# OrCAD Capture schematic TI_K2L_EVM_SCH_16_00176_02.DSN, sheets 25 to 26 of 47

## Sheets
25 PAGE42 : K2L_POWER SECTION 1: size C; title: 12v input (fused), 12v to 3p3v MP, K2L VID, 1p8 to VPP1p8 switch, 3v3Aux to 3v3, FMC1 Power (fuse),
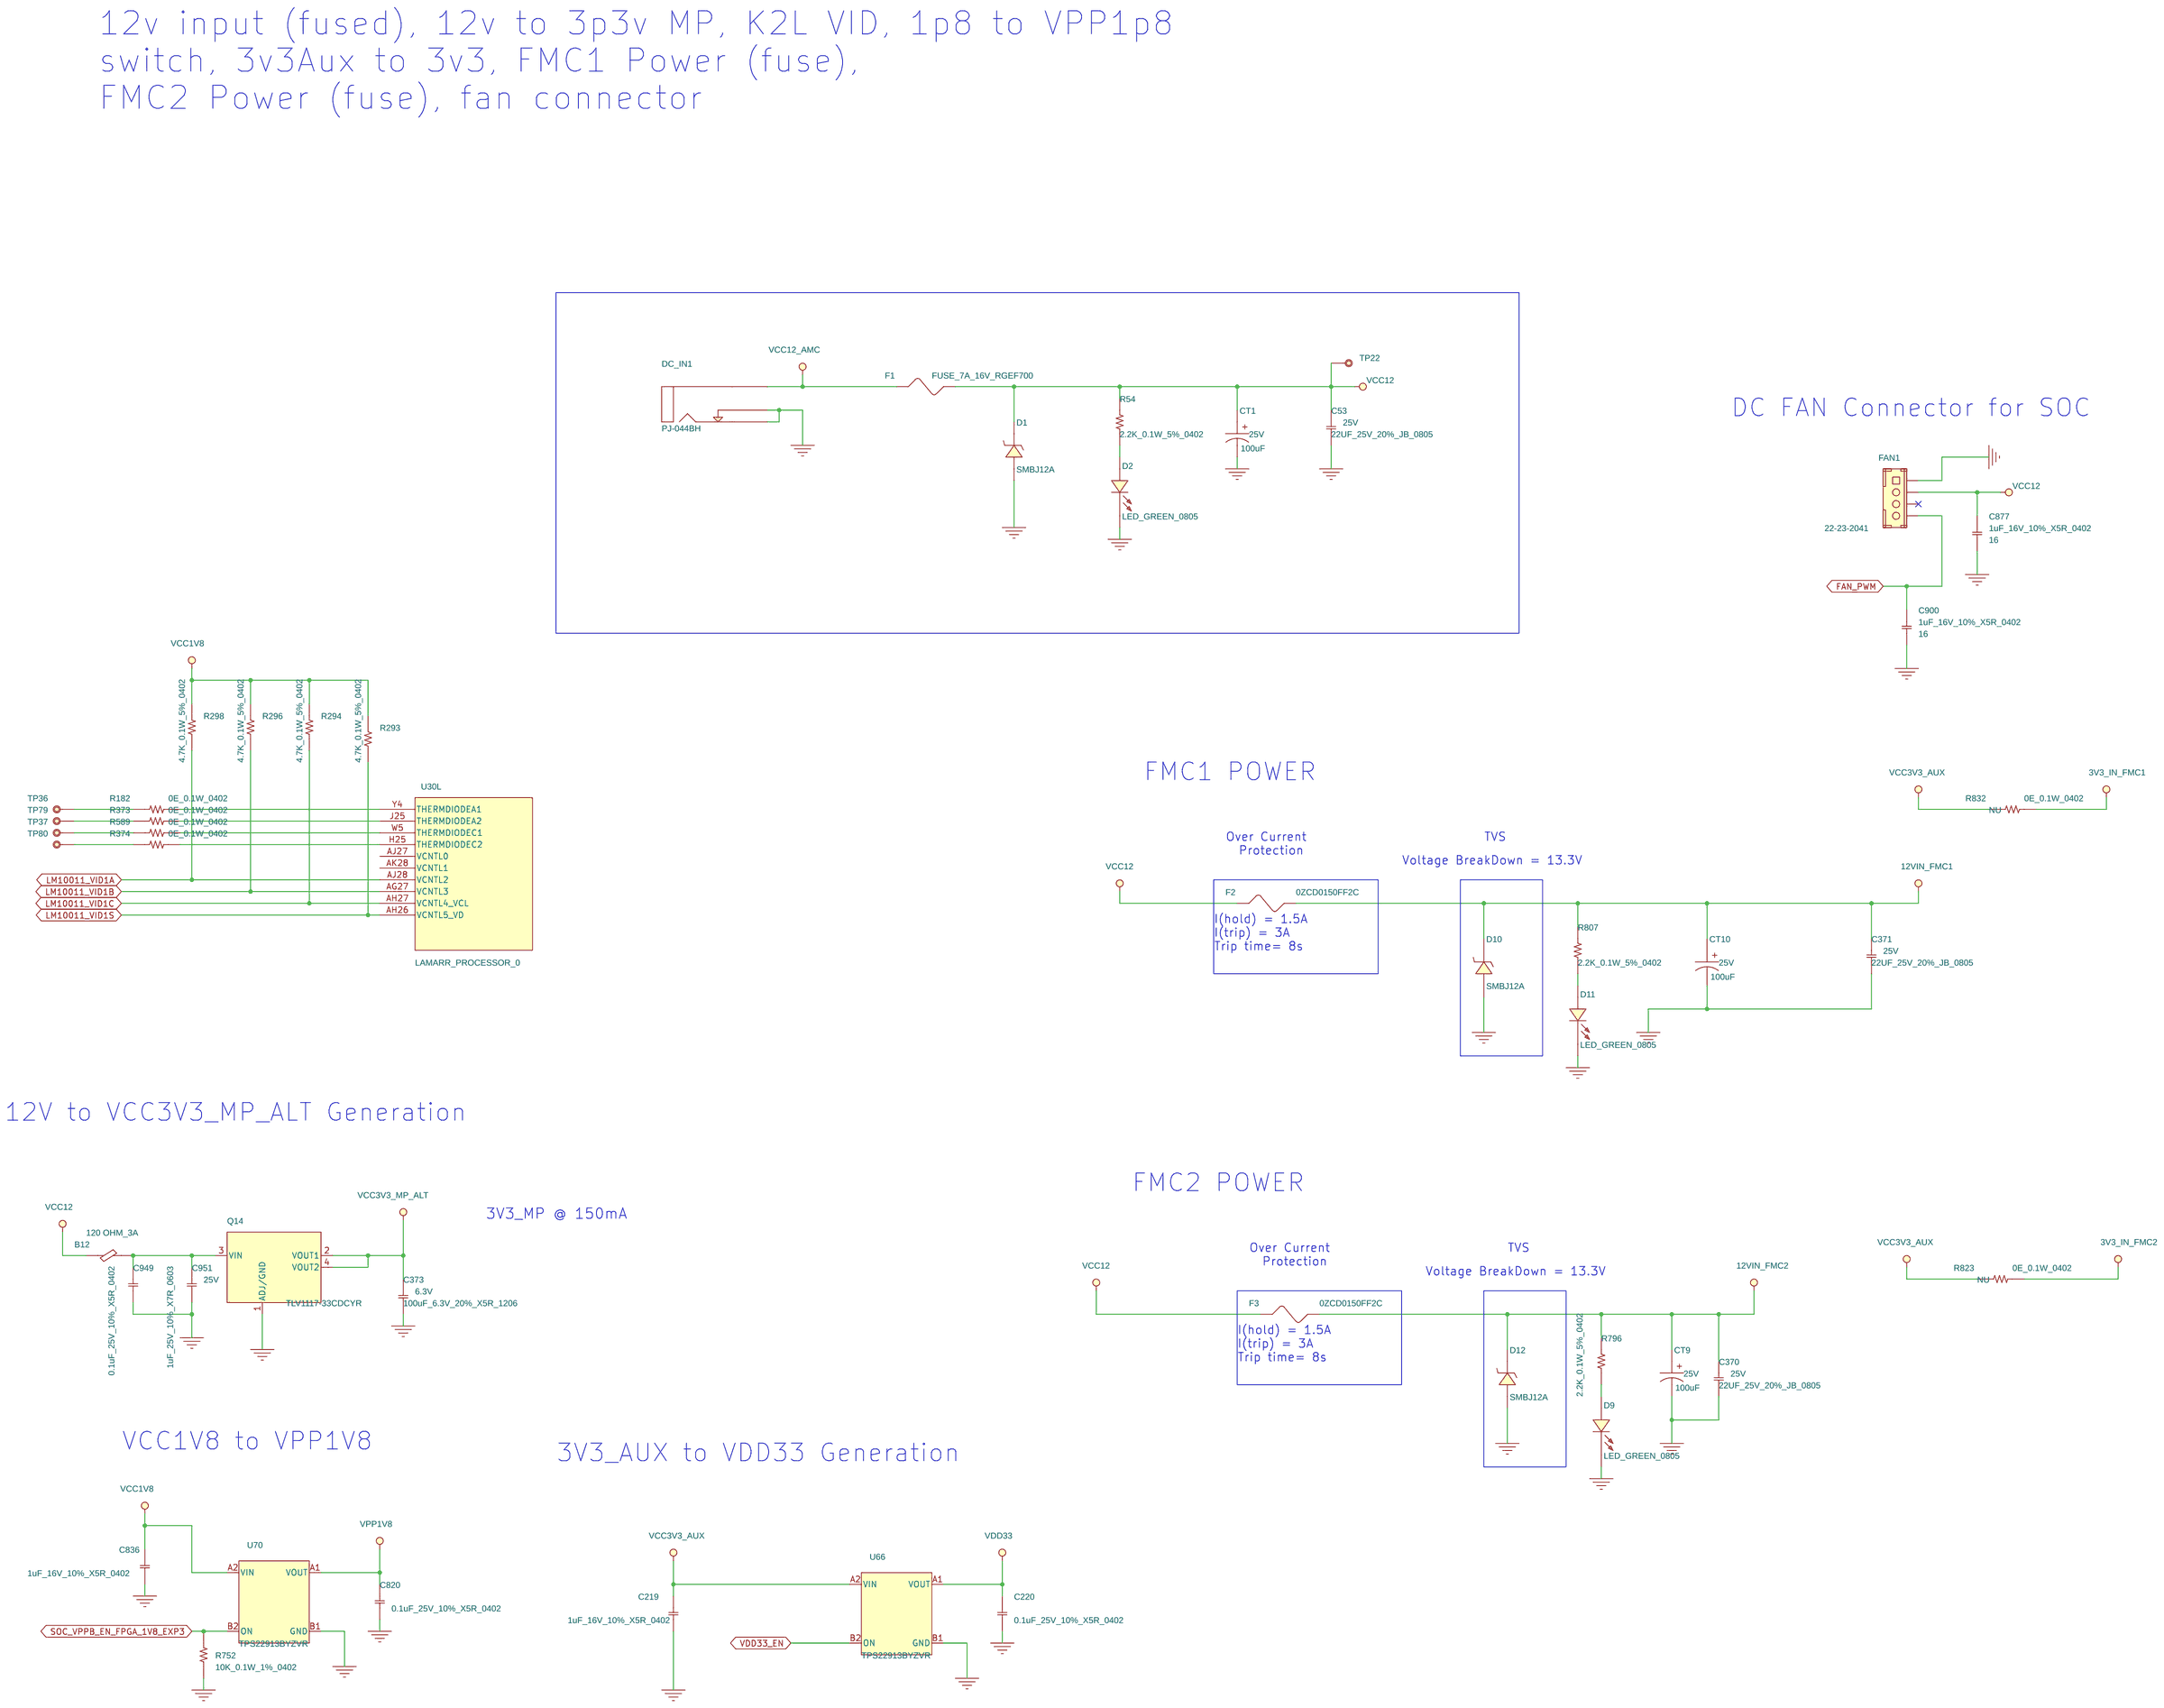
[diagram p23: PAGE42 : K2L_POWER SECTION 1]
26 PAGE26 : K2L_EXPANSION_CONN: size C; title: Expansion Connector, I2C SOC to Expander 1.8v/3.3vAux
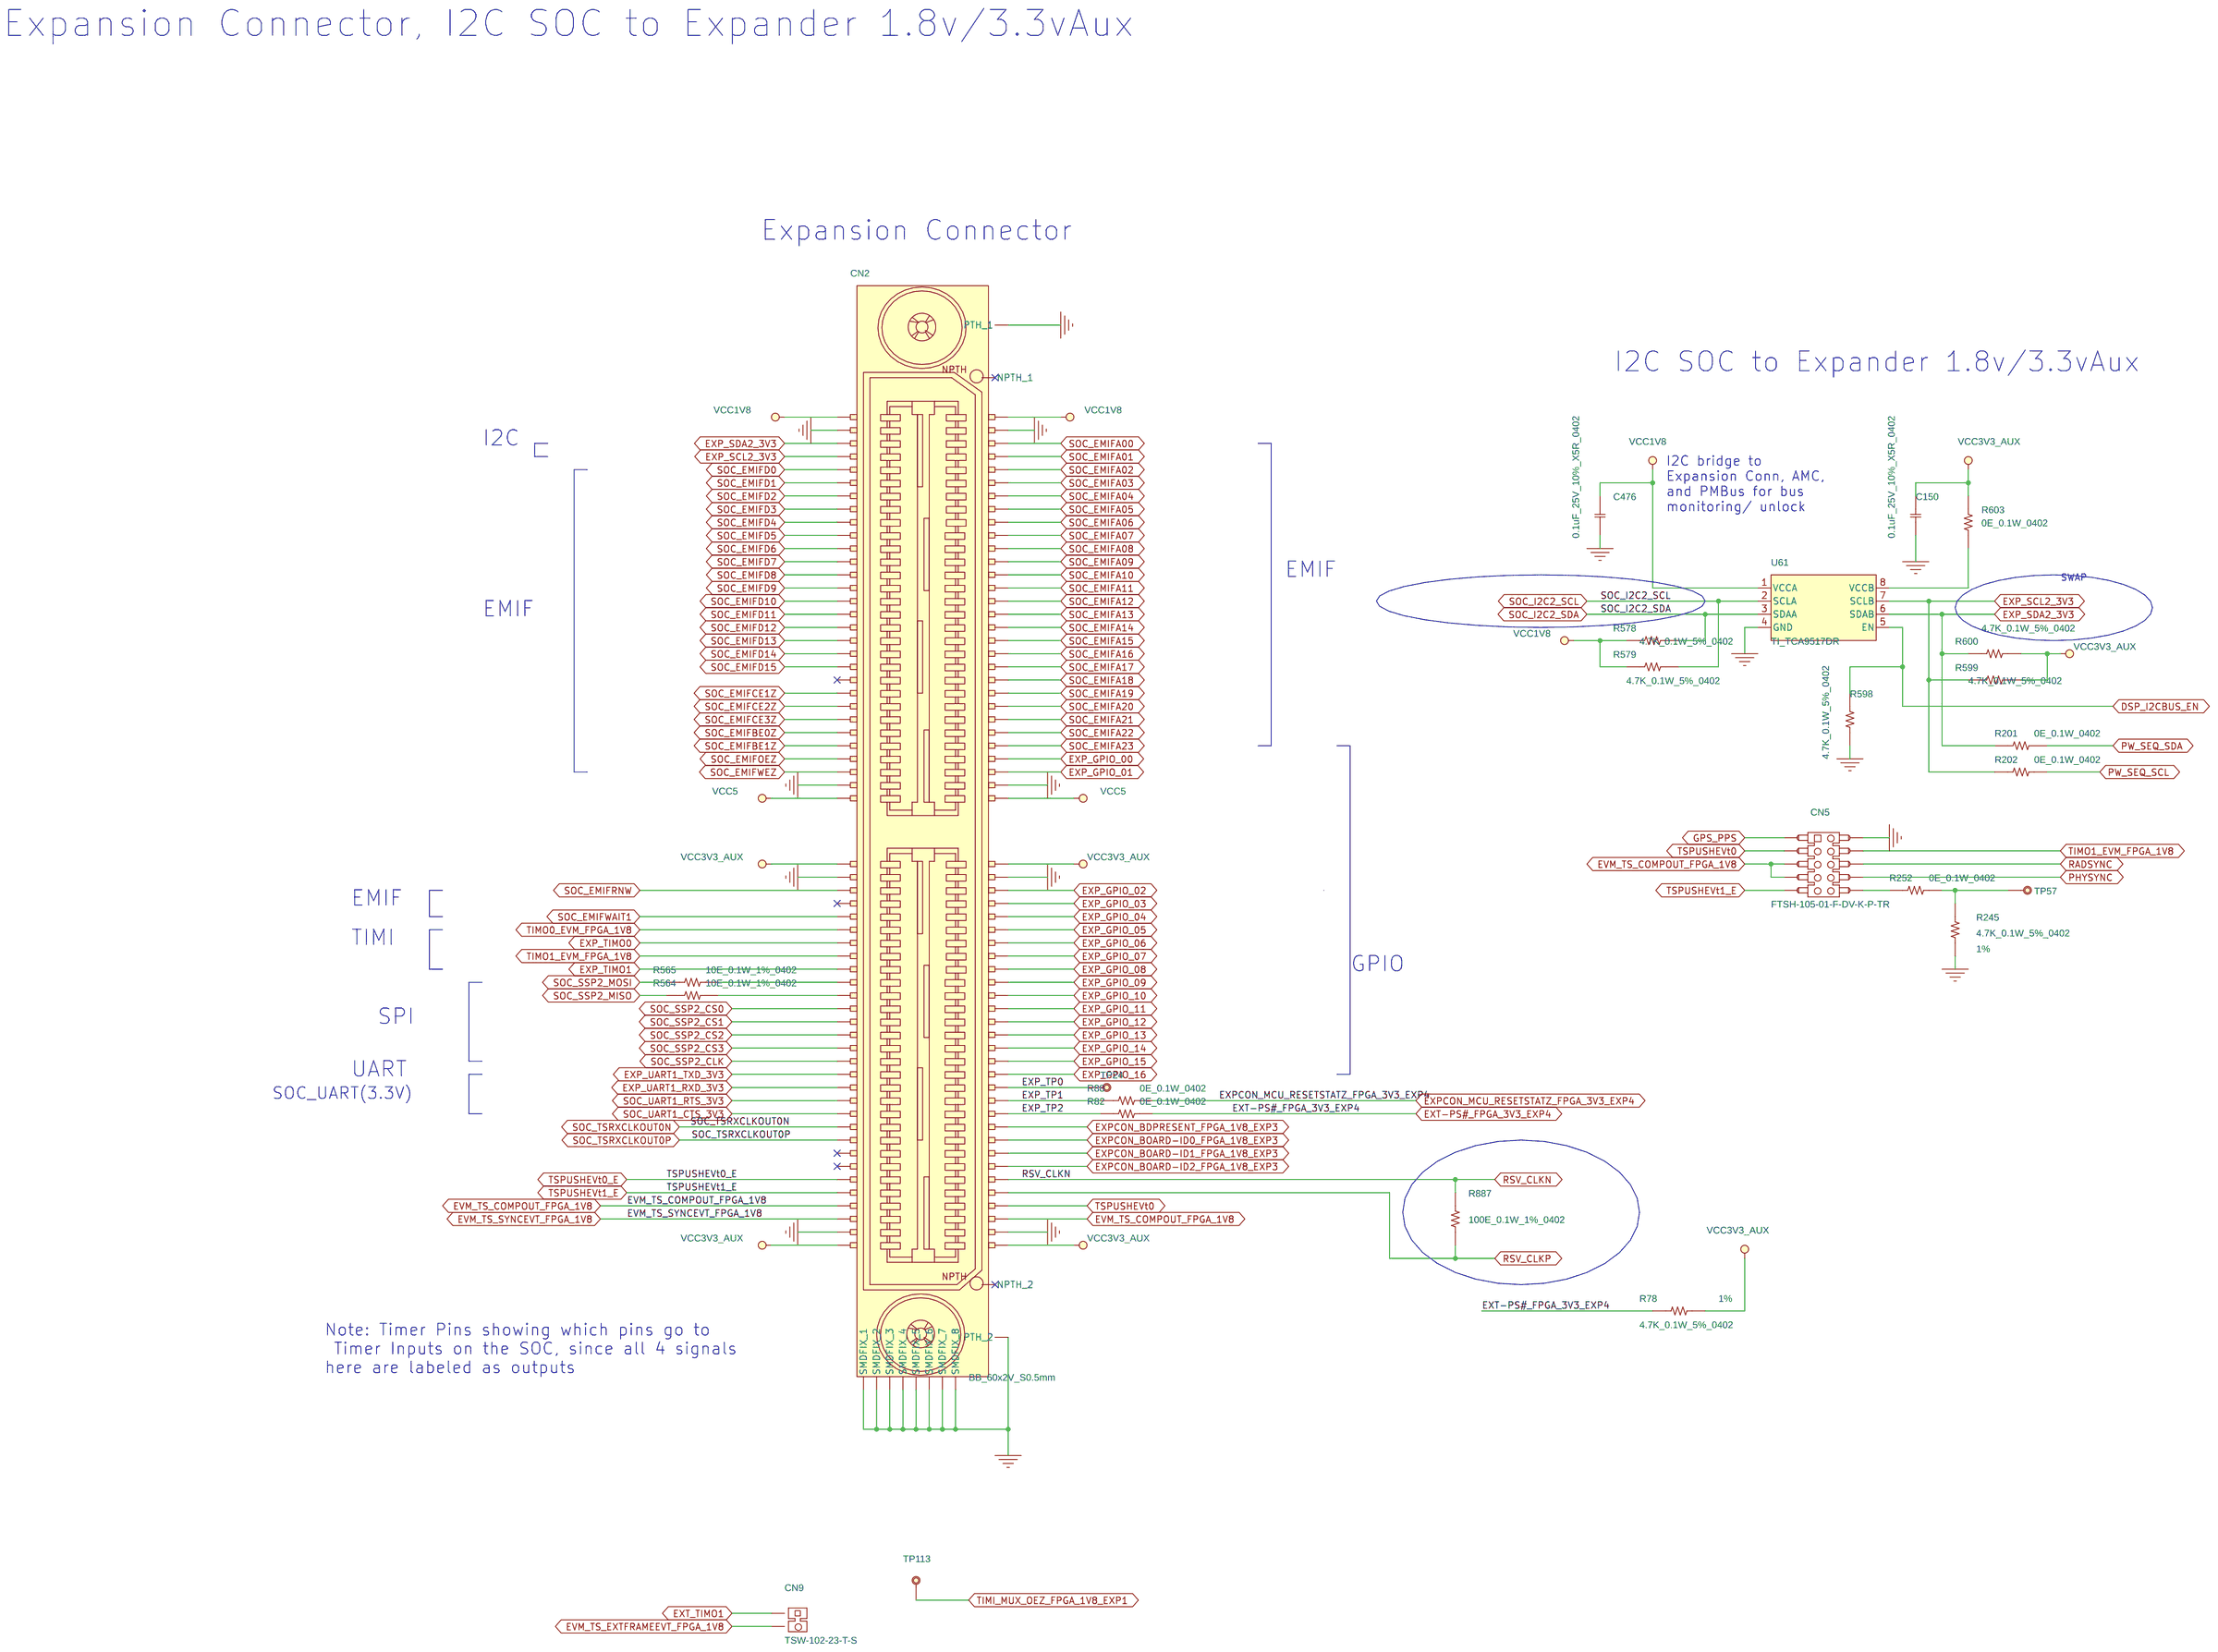
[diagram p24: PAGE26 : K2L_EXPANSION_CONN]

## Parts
sheet PAGE24 : K2L_JTAG
U30  LAMARR_PROCESSOR_0  [SKTBGA_Z3566_SS900-RHFB-BGA080]  (sections A,B,C,D,E,F,G,H,I,J,K,L,M,N,O,P,Q,R,S,T,U)
sheet PAGE26 : K2L_EXPANSION_CONN
C150  0.1uF_25V_10%_X5R_0402  [C0402]
C476  0.1uF_25V_10%_X5R_0402  [C0402]
CN2  BB_60x2V_S0.5mm  [BB_60x2P_20_2225x285_F]
CN5  FTSH-105-01-F-DV-K-P-TR  [HD_5x2P_50_H235]
CN9  TSW-102-23-T-S  [SAMTSW-102-22-T-S]
R78  4.7K_0.1W_5%_0402  [R0402]
R82  0E_0.1W_0402  [R0402]
R88  0E_0.1W_0402  [R0402]
R201  0E_0.1W_0402  [R0402]
R202  0E_0.1W_0402  [R0402]
R245  4.7K_0.1W_5%_0402  [R0402]
R252  0E_0.1W_0402  [R0402]
R564  10E_0.1W_1%_0402  [R0402]
R565  10E_0.1W_1%_0402  [R0402]
R578  4.7K_0.1W_5%_0402  [R0402]
R579  4.7K_0.1W_5%_0402  [R0402]
R598  4.7K_0.1W_5%_0402  [R0402]
R599  4.7K_0.1W_5%_0402  [R0402]
R600  4.7K_0.1W_5%_0402  [R0402]
R603  0E_0.1W_0402  [R0402]
R887  100E_0.1W_1%_0402  [R0402]
TP24  TP  [TP-S40]
TP57  TP  [TP-S40]
TP113  TP  [TP-S40]
U61  TI_TCA9517DR  [SOIC_8P_50_193X236]
sheet PAGE42 : K2L_POWER SECTION 1
B12  120 OHM_3A  [L0603]
C53  22UF_25V_20%_JB_0805  [C0805]
C219  1uF_16V_10%_X5R_0402  [C0402]
C220  0.1uF_25V_10%_X5R_0402  [C0402]
C370  22UF_25V_20%_JB_0805  [C0805]
C371  22UF_25V_20%_JB_0805  [C0805]
C373  100uF_6.3V_20%_X5R_1206  [C1206-1]
C820  0.1uF_25V_10%_X5R_0402  [C0402]
C836  1uF_16V_10%_X5R_0402  [C0402]
C877  1uF_16V_10%_X5R_0402  [C0402]
C900  1uF_16V_10%_X5R_0402  [C0402]
C949  0.1uF_25V_10%_X5R_0402  [C0402]
C951  1uF_25V_10%_X7R_0603  [C0603]
CT1  100uF  [CT7343]
CT9  100uF  [CT7343]
CT10  100uF  [CT7343]
D1  SMBJ12A  [DIO_DO214AA_SMB]
D2  LED_GREEN_0805  [LED_LTST-C171]
D9  LED_GREEN_0805  [LED_LTST-C171]
D10  SMBJ12A  [DIO_DO214AA_SMB]
D11  LED_GREEN_0805  [LED_LTST-C171]
D12  SMBJ12A  [DIO_DO214AA_SMB]
DC_IN1  PJ-044BH  [CUI_PJ-044BH]
F1  FUSE_7A_16V_RGEF700  [PTC_RGEF700]
F2  0ZCD0150FF2C  [FUSE_0ZCD0150FF2C]
F3  0ZCD0150FF2C  [FUSE_0ZCD0150FF2C]
FAN1  22-23-2041  [MOL22-23-2041]
Q14  TLV1117-33CDCYR  [SOT-223]
R54  2.2K_0.1W_5%_0402  [R0402]
R182  0E_0.1W_0402  [R0402]
R293  4.7K_0.1W_5%_0402  [R0402]
R294  4.7K_0.1W_5%_0402  [R0402]
R296  4.7K_0.1W_5%_0402  [R0402]
R298  4.7K_0.1W_5%_0402  [R0402]
R373  0E_0.1W_0402  [R0402]
R374  0E_0.1W_0402  [R0402]
R589  0E_0.1W_0402  [R0402]
R752  10K_0.1W_1%_0402  [R0402]
R796  2.2K_0.1W_5%_0402  [R0402]
R807  2.2K_0.1W_5%_0402  [R0402]
R823  0E_0.1W_0402  [R0402]
R832  0E_0.1W_0402  [R0402]
TP22  TP  [TP-S40]
TP36  TP  [TP-S40]
TP37  TP  [TP-S40]
TP79  TP  [TP-S40]
TP80  TP  [TP-S40]
U66  TPS22913BYZVR  [dsbga50p_0p9x0p9_4]
U70  TPS22913BYZVR  [dsbga50p_0p9x0p9_4]

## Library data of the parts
U30 = LAMARR_PROCESSOR_7: LAMARR-SoC 900BGA 4DSP + 2ARM; Color: Default; Distributor_name: TBD; Distributor_part_number: TBD; EIC Part#: TBD; Location X-Coordinate: 0; Location Y-Coordinate: 0; Manufacture: TI; Manufacture Part Number: TCI6630K2L; Manufacture(English): TI; Manufacture_Part_Number: TCI6630K2L; Manufacturer: TI; Manufacturer_Part_No: TCI6630K2L; Mfg: TI; Mfg Part#: TBD; Mfr_name: TI; Mfr_part_number: LAMARR-SoC; Price @ 1: TBD; Price @ 10K: TBD; Price @ 1K: TBD; Primitive: DEFAULT; SPLIT_INST: TRUE; SWAP_INFO: (S1+S2+S3+S4+S5+S6+S7+S8+S9+S10+S11+S12+S13+S14+S15+S16+S17+S18+S19+S20+S21); Vendor: TBD; Vendor_Part_No: TBD; eI Part#: TBD
C150 C476 = 11_C_0: CAP CER 0.1UF 25V 10% X5R 0402; Avalue_Part_Number: E1123510400H; Distributor_name: DIGIKEY; Distributor_part_number: 445-4964-1-ND; EIC Part#: 03_00470_02; MOUNTED: <MOUNTED>; Manufacture: TDK Corporation; Manufacture Part Number: C1005X5R1E104K050BC; Manufacture(English): TDK Corporation; Manufacture_Part_Number: GRM155R71C104KA88D; Manufacturer: TDK Corporation; Manufacturer_Part_No: C1005X5R1E104K050BC; Mfg: Murata Electronics North America; Mfg Part#: 03_00470_02; Mfr_name: TDK Corporation; Mfr_part_number: C1005X5R1E104K050BC; Package: 0402; Price @ 1: 0.10000; Price @ 1K: 0.00420; ProcessType: SMT; Tolerance: 10%; Vendor: DIGIKEY; Vendor Part#: 445-4964-1-ND; Vendor_Part_No: 445-4964-1-ND; eI Part#: 03_00470_02
CN2 = 1654_BB_60X2P_4HOLD_QSH_0: CONN RECPT 120POS 0.5MM SMT; Distributor_name: DIGIKEY; Distributor_part_number: QSH-060-01-L-D-A-RT1-ND; EIC Part#: TBD; Manufacture: Samtec Inc; Manufacture Part Number: QSH-060-01-L-D-A-RT1; Manufacture(English): Samtec Inc; Manufacture_Part_Number: QSH-060-01-L-D-A-RT1; Manufacturer: Samtec Inc; Manufacturer_Part_No: QSH-060-01-L-D-A-RT1; Mfg: Samtec Inc; Mfg Part#: TBD; Mfr_name: Samtec Inc; Mfr_part_number: QSH-060-01-L-D-A-RT1; Package: BB60x2P-S0.5; Part_Number: 1654010650-01; Price @ 1K: 12.95750; ProcessType: SMT; Vendor: DIGIKEY; Vendor_Part_No: QSH-060-01-L-D-A-RT1-ND; eI Part#: TBD
CN5 = 1653_HD_5X2P_0: CONN HEADER 10POS DUAL .05 SMD; AVL_Part: AVL; Distributor_name: DIGIKEY; Distributor_part_number: FTSH-105-01-F-DV-K-P-TR-ND; EIC Part#: TBD; Manufacture: Samtec Inc; Manufacture(English): Samtec Inc; Manufacturer: Samtec Inc; Mfg: Samtec Inc; Mfg Part#: TBD; Mfr_name: Samtec Inc; Package: PH5x2P-S1.27; Part_Number: 1653004493; Price @ 1: 2.19000; Price @ 10K: 1.88000; Price @ 1K: 2.00000; ProcessType: SMT; Vendor: DIGIKEY; Vendor_Part_No: FTSH-105-01-F-DV-K-P-TR-ND; eI Part#: TBD
CN9 = 1653_HD_2P_D_0: CONN HEADER 2POS .100 SNGL TIN; AVL_Part: AVL; Advansus_Part_Number: 12G06010002DAD; Avalue_Part_Number: E1653002101R; Distributor_name: DIGIKEY; Distributor_part_number: SAM1075-02-ND; EIC Part#: 09_00957_01; Manufacture: Samtec Inc; Manufacture(English): Samtec Inc; Manufacturer: Samtec Inc; Mfg: Samtec Inc; Mfg Part#: 09_00957_01; Mfr_name: Samtec Inc; Package: PH2x1P-2.00; Part_Number: 1653002101-03; Price @ 1: 0.49000; Price @ 10K: 0.21284; Price @ 1K: 0.24263; ProcessType: DIP; Vendor: DIGIKEY; Vendor_Part_No: SAM1075-02-ND; eI Part#: TBD
R78 R245 R578 R579 R599 R600 = 10_R_0: RES 4.7K OHM 1/10W 5% 0402 SMD; AVL_Part: AVL; Advansus_Part_Number: 10G212470114030; Characteristic: 1%; Distributor_name: DIGIKEY; Distributor_part_number: P4.7KJCT-ND; EIC Part#: 02_00023_01; MOUNTED: <MOUNTED>; Manufacture: Panasonic - ECG; Manufacture Part Number: ERJ-2GEJ472X; Manufacture(English): Panasonic - ECG; Manufacture_Part_Number: ERJ-2GEJ472X; Manufacturer: Panasonic - ECG; Manufacturer_Part_No: ERJ-2GEJ472X; Mfg: Panasonic Electronic Components; Mfg Part#: 02_00266_01; Mfr_name: Panasonic - ECG; Mfr_part_number: ERJ-2GEJ472X; Package: 0402; Part_Number: 1000000558-04; Price @ 1: 0.10000; Price @ 10K: 0.00347; Price @ 1K: 0.00672; ProcessType: SMT; Tolerance: 1%; Vendor: DIGIKEY; Vendor_Part_No: P4.7KJCT-ND; eI Part#: 02_00023_01
R82 R88 = 10_R_0: RES 0.0 OHM 1/10W JUMP 0402 SMD; Characteristic: 5%; Distributor_name: DIGIKEY; Distributor_part_number: P0.0JCT-ND; EIC Part#: 02_00019_01; Manufacture: Panasonic - ECG; Manufacture Part Number: ERJ-2GE0R00X; Manufacture(English): Panasonic - ECG; Manufacture_Part_Number: ERJ-2GE0R00X; Manufacturer: Panasonic - ECG; Manufacturer_Part_No: ERJ-2GE0R00X; Mfg: Panasonic Electronic Components; Mfg Part#: 02_00019_01; Mfr_name: Panasonic - ECG; Mfr_part_number: ERJ-2GE0R00X; Package: 0402; Part_Number: 105A700004; Price @ 1: 0.05000; Price @ 10K: 0.00248; Price @ 1K: 0.00480; ProcessType: SMT; Tolerance: 5%; Vendor: DIGIKEY; Vendor_Part_No: P0.0JCT-ND; eI Part#: 02_00019_01
R182 R201 R202 R252 R373 R374 R589 = 10_R_0: RES 0.0 OHM 1/10W JUMP 0402 SMD; Alt Mfg: Yageo; Distributor_name: DIGIKEY; Distributor_part_number: P0.0JCT-ND; EIC Part#: 02_00019_01; Manufacture: Panasonic - ECG; Manufacture Part Number: ERJ-2GE0R00X; Manufacture(English): Panasonic - ECG; Manufacture_Part_Number: ERJ-2GE0R00X; Manufacturer: Panasonic - ECG; Manufacturer_Part_No: ERJ-2GE0R00X; Mfg Part#: 02_00019_01; Mfr_name: Panasonic - ECG; Mfr_part_number: ERJ-2GE0R00X; Oper. Temp. Range: -55C to 125C; Package: 0402; ProcessType: SMT; Remark: Alt part is 1/16W; RoHS: Yes; Tolerance: 5%; Vendor: DIGIKEY; Vendor Part#: P0.0JCT-ND; Vendor_Part_No: P0.0JCT-ND; eI Part#: 02_00019_01
R564 R565 = 10_R_0: RES 10.0 OHM 1/10W 1% 0402 SMD; Characteristic: 5%; Distributor_name: DIGIKEY; Distributor_part_number: P10.0LCT-ND; EIC Part#: 02_00348_01; Manufacture: Panasonic - ECG; Manufacture Part Number: ERJ-2RKF10R0X; Manufacture(English): Panasonic - ECG; Manufacture_Part_Number: ERJ-2RKF10R0X; Manufacturer: Panasonic - ECG; Manufacturer_Part_No: ERJ-2RKF10R0X; Mfg: Panasonic Electronic Components; Mfg Part#: ERJ-2RKF10R0X; Mfr_name: Panasonic - ECG; Mfr_part_number: ERJ-2RKF10R0X; Package: 0402; Part_Number: 105A701004; Price @ 1: 0.10000; Price @ 10K: 0.00248; Price @ 1K: 0.00480; ProcessType: SMT; Tolerance: 5%; Vendor: DIGIKEY; Vendor_Part_No: P10.0LCT-ND; eI Part#: 02_00348_01
R598 = 10_R_0: RES 4.7K OHM 1/10W 5% 0402 SMD; Alt Mfg: Yageo; Alt Mfg Part#: RC0402JR-074K7L; Distributor_name: DIGIKEY; Distributor_part_number: P4.7KJCT-ND; EIC Part#: 02_00023_01; Manufacture: Panasonic - ECG; Manufacture Part Number: ERJ-2GEJ472X; Manufacture(English): Panasonic - ECG; Manufacture_Part_Number: ERJ-2GEJ472X; Manufacturer: Panasonic - ECG; Manufacturer_Part_No: ERJ-2GEJ472X; Mfg Part#: 02_00023_01; Mfr_name: Panasonic - ECG; Mfr_part_number: ERJ-2GEJ472X; Oper. Temp. Range: -55C to 125C; Package: 0402; ProcessType: SMT; Remark: Alt part is 1/16W; RoHS: Yes; Tolerance: 1%; Vendor: DIGIKEY; Vendor Part#: P4.7KJCT-ND; Vendor_Part_No: P4.7KJCT-ND; eI Part#: 02_00023_01
R603 = 10_R_0: RES 0.0 OHM 1/10W JUMP 0402 SMD; Characteristic: 5%; Distributor_name: DIGIKEY; Distributor_part_number: P0.0JCT-ND; EIC Part#: 02_00019_01; MOUNTED: <MOUNTED>; Manufacture: Panasonic - ECG; Manufacture Part Number: ERJ-2GE0R00X; Manufacture(English): Panasonic - ECG; Manufacture_Part_Number: ERJ-2GE0R00X; Manufacturer: Panasonic - ECG; Manufacturer_Part_No: ERJ-2GE0R00X; Mfg: Panasonic Electronic Components; Mfg Part#: 02_00019_01; Mfr_name: Panasonic - ECG; Mfr_part_number: ERJ-2GE0R00X; Package: 0402; Part_Number: 105A700004; Price @ 1: 0.05000; Price @ 10K: 0.00248; Price @ 1K: 0.00480; ProcessType: SMT; Tolerance: 5%; Vendor: DIGIKEY; Vendor_Part_No: P0.0JCT-ND; eI Part#: 02_00019_01
R887 = 10_R_0: RES 100 OHM 1/10W 1% 0402 SMD; Characteristic: 1%; Distributor_name: DIGIKEY; Distributor_part_number: P100LCT-ND; EIC Part#: 02_00043_02; Manufacture: Panasonic - ECG; Manufacture Part Number: ERJ-2RKF1000X; Manufacture(English): Panasonic - ECG; Manufacture_Part_Number: ERJ-2RKF1000X; Manufacturer: Panasonic - ECG; Manufacturer_Part_No: ERJ-2RKF1000X; Mfg: Panasonic Electronic Components; Mfg Part#: 02_00043_02; Mfr_name: Panasonic - ECG; Mfr_part_number: ERJ-2RKF1000X; Package: 0402; Part_Number: 105A510004; Price @ 1: 0.10000; Price @ 10K: 0.00347; Price @ 1K: 0.00672; ProcessType: SMT; Tolerance: 1%; Vendor: DIGIKEY; Vendor_Part_No: P100LCT-ND; eI Part#: 02_00019_01
TP22 TP24 TP36 TP37 TP57 TP79 TP80 = 00_TP28_0: TEST PAD TP; Advansus_Part_Number: 0030000003; Avalue_Part_Number: 0030000003; Distributor_name: NA; Distributor_part_number: NA; EIC Part#: NA; Manufacture: NA; Manufacture Part Number: NA; Manufacture(English): NA; Manufacture_Part_Number: NA; Manufacturer: NA; Manufacturer_Part_No: NA; Mfg: NA; Mfg Part#: NA; Mfr_name: NA; Mfr_part_number: NA; Part_Number: 0030000003; Price @ 1: NA; Price @ 10K: NA; Price @ 1K: NA; ProcessType: SMT; Vendor: NA; Vendor_Part_No: NA; eI Part#: NA
TP113 = 00_TP28_0: TEST PAD TP; Advansus_Part_Number: 0030000003; Avalue_Part_Number: 0030000003; Distributor_name: NA; Distributor_part_number: NA; EIC Part#: NA; Manufacture: NA; Manufacture Part Number: NA; Manufacture(English): NA; Manufacture_Part_Number: NA; Manufacturer: NA; Manufacturer_Part_No: NA; Mfg: NA; Mfg Part#: NA; Mfr_name: NA; Mfr_part_number: NA; Part_Number: 0030000003; Price @ 1: NA; Price @ 10K: NA; Price @ 1K: NA; ProcessType: SMT; Vendor: NA; Vendor_Part_No: NA; eI Part#: TBD
U61 = 141_TI_PCA9517DR_0: IC LVL-TRANSL I2C BUS REP 8-SOIC; AVL_Part: AVL; Alternate_Mfr: TI; Alternate_Partno: TCA9517DR; Distributor_name: DIGIKEY; Distributor_part_number: 296-23734-1-ND; EIC Part#: TBD; Manufacture: TI; Manufacture Part Number: PCA9517DR; Manufacture(English): TI; Manufacture_Part_Number: PCA9517DR; Manufacturer: TI; Manufacturer_Part_No: PCA9517DR; Mfg: TI; Mfg Part#: TBD; Mfr_name: TI; Mfr_part_number: PCA9517DR; Package: SOIC8; Part_Number: 1410015122; Price @ 1: 2.94000; Price @ 10K: 1.35660; Price @ 1K: 1.46880; ProcessType: SMT; Vendor: DIGIKEY; Vendor_Part_No: 296-23734-1-ND; eI Part#: 01_00923_01
B12 = 1212_BEAD_0: FILTER CHIP 120 OHM 3A 0603; Distributor_name: DIGIKEY; Distributor_part_number: 490-3996-1-ND; EIC Part#: 04_00405_01; Manufacture: Murata; Manufacture Part Number: BLM18SG121TN1D; Manufacture(English): Murata; Manufacture_Part_Number: BLM18SG121TN1D; Manufacturer: Murata; Manufacturer_Part_No: BLM18SG121TN1D; Mfg: Murata Electronics North America; Mfg Part#: 04_00405_01; Mfr_name: Murata; Mfr_part_number: BLM18SG121TN1D; Part_Number: 1212002506; Price @ 1: 0.14000; Price @ 10K: 0.03173; Price @ 1K: 0.03878; RoHS: Yes; Vendor: DIGIKEY; Vendor Part#: 490-3996-1-ND; Vendor_Part_No: 490-3996-1-ND; eI Part#: 04_00405_01
C53 C370 C371 = 11_C_0: CAP CER 22UF 25V 20% JB 0805; Alternate_Mfr: Samsung; Alternate_Partno: CL21A226MAQNNNE; Distributor_name: DIGIKEY; Distributor_part_number: 445-11475-2-ND; EIC Part#: 03_00586_01; Manufacture: TDK Corporation; Manufacture Part Number: C2012JB1E226M125AC; Manufacture(English): TDK Corporation; Manufacture_Part_Number: C2012JB1E226M125AC; Manufacturer: TDK Corporation; Manufacturer_Part_No: C2012JB1E226M125AC; Mfg: TDK Corporation; Mfg Part#: C2012JB1E226M125AC; Mfr_name: TDK Corporation; Mfr_part_number: C2012JB1E226M125AC; Oper. Temp. Range: -55C to 85C; Package: 0805; Price @ 1: 1.09000; Price @ 10K: 0.26265; Price @ 1K: 0.37647; ProcessType: SMT; RoHS: Yes; Tolerance: 10%; Vendor: DIGIKEY; Vendor Part#: 490-5527-1-ND; Vendor_Part_No: 03_00586_01; Voltage: 25V; eI Part#: 03_00586_01
C219 C836 = 11_C_12: CAP CER 1UF 16V 10% X5R 0402; Characteristic: <Characteristic>; Distributor_name: DIGIKEY; Distributor_part_number: 445-4978-1-ND; EIC Part#: 03_00355_04; Manufacture: TDK Corporation; Manufacture Part Number: C1005X5R1C105K050BC; Manufacture(English): TDK Corporation; Manufacture_Part_Number: C1005X5R1C105K050BC; Manufacturer: TDK Corporation; Manufacturer_Part_No: C1005X5R1C105K050BC; Mfg: TDK Corporation; Mfg Part#: C1005X5R1C105K050BC; Mfr_name: TDK Corporation; Mfr_part_number: C1005X5R1C105K050BC; Oper. Temp. Range: -55C to 85C; Package: 0402; Price @ 1: 0.12000; Price @ 10K: 0.01600; Price @ 1K: 0.02200; ProcessType: SMT; RoHS: Yes; Tolerance: 10%; Vendor: DIGIKEY; Vendor Part#: 445-4978-1-ND; Vendor_Part_No: 445-4978-1-ND; Voltage: 6.3V; eI Part#: 03_00355_04
C220 C820 = 11_C_12: CAP CER 0.1UF 25V 10% X5R 0402; Alt Mfg: Taiyo Yuden; Distributor_name: DIGIKEY; Distributor_part_number: 445-4964-1-ND; EIC Part#: 03_00470_02; Manufacture: TDK Corporation; Manufacture Part Number: C1005X5R1E104K050BC; Manufacture(English): TDK Corporation; Manufacture_Part_Number: GRM155R61E104KA87D; Manufacturer: TDK Corporation; Manufacturer_Part_No: C1005X5R1E104K050BC; Mfg: Murata Electronics North America; Mfg Part#: 03_00470_02; Mfr_name: TDK Corporation; Mfr_part_number: C1005X5R1E104K050BC; Oper. Temp. Range: -55°C ~ 85°C; Package: 0402; Price @ 1: 0.10000; Price @ 1K: 0.00960; ProcessType: SMT; RoHS: Yes; Tolerance: 10%; Vendor: DIGIKEY; Vendor Part#: 445-4964-1-ND; Vendor_Part_No: 445-4964-1-ND; eI Part#: 03_00470_02
C373 = 11_C_0: CAP CER 100UF 6.3V 20% X5R 1206; Distributor_name: DIGIKEY; Distributor_part_number: 587-1453-1-ND; EIC Part#: 03_00380_04; Manufacture: Taiyo Yuden; Manufacture Part Number: JMK316BJ107ML-T; Manufacture(English): Taiyo Yuden; Manufacture_Part_Number: JMK316BJ107ML-T; Manufacturer: Taiyo Yuden; Manufacturer_Part_No: JMK316BJ107ML-T; Mfg: Taiyo Yuden; Mfg Part#: 03_00380_04; Mfr_name: Taiyo Yuden; Mfr_part_number: JMK316BJ107ML-T; Oper. Temp. Range: -55C to 85C; Package: 1206; Price @ 1: 1.80000; Price @ 10K: 0.30450; Price @ 1K: 0.43050; ProcessType: SMT; RoHS: Yes; Tolerance: 20%; Vendor: DIGIKEY; Vendor Part#: 587-1963-1-ND; Vendor_Part_No: 587-1453-1-ND; Voltage: 6.3V; eI Part#: 03_00380_04
C877 C900 = 11_C_12: CAP CER 1UF 16V 10% X5R 0402; Characteristic: <Characteristic>; Distributor_name: DIGIKEY; Distributor_part_number: 445-4978-1-ND; EIC Part#: 03_00355_04; Manufacture: TDK Corporation; Manufacture Part Number: C1005X5R1C105K050BC; Manufacture(English): TDK Corporation; Manufacture_Part_Number: C1005X5R1C105K050BC; Manufacturer: TDK Corporation; Manufacturer_Part_No: C1005X5R1C105K050BC; Mfg: TDK Corporation; Mfg Part#: C1005X5R1C105K050BC; Mfr_name: TDK Corporation; Mfr_part_number: C1005X5R1C105K050BC; Oper. Temp. Range: -55C to 85C; Package: 0402; Price @ 1: 0.12000; Price @ 10K: 0.01600; Price @ 1K: 0.02200; ProcessType: SMT; RoHS: Yes; Tolerance: 10%; Vendor: DIGIKEY; Vendor Part#: 445-4978-1-ND; Vendor_Part_No: 445-4978-1-ND; Voltage: 16; eI Part#: 03_00355_04
C949 = 11_C_0: CAP CER 0.1UF 25V 10% X5R 0402; Alt Mfg: Taiyo Yuden; Distributor_name: DIGIKEY; Distributor_part_number: 445-4964-1-ND; EIC Part#: 03_00470_02; Manufacture: TDK Corporation; Manufacture Part Number: C1005X5R1E104K050BC; Manufacture(English): TDK Corporation; Manufacture_Part_Number: GRM155R61E104KA87D; Manufacturer: TDK Corporation; Manufacturer_Part_No: C1005X5R1E104K050BC; Mfg: Murata Electronics North America; Mfg Part#: 03_00470_02; Mfr_name: TDK Corporation; Mfr_part_number: C1005X5R1E104K050BC; Oper. Temp. Range: -55°C ~ 85°C; Package: 0402; Price @ 1: 0.10000; Price @ 1K: 0.00960; ProcessType: SMT; RoHS: Yes; Tolerance: 10%; Vendor: DIGIKEY; Vendor Part#: 445-4964-1-ND; Vendor_Part_No: 445-4964-1-ND; eI Part#: 03_00470_02
C951 = 11_C_0: CAP CER 1UF 25V 10% X5R 0603; Distributor_name: DIGIKEY; Distributor_part_number: 490-3897-1-ND; EIC Part#: 03_00161_02; Manufacture: Murata; Manufacture Part Number: GRM188R61E105KA12D; Manufacture(English): Murata; Manufacture_Part_Number: GRM188R71E105KA12D; Manufacturer: Murata; Manufacturer_Part_No: GRM188R61E105KA12D; Mfg: Murata; Mfg Part#: 03_00161_02; Mfr_name: Murata; Mfr_part_number: GRM188R61E105KA12D; Oper. Temp. Range: -55C to 85C; Package: 0603; Price @ 1: 0.38000; Price @ 10K: 0.07363; Price @ 1K: 0.09353; ProcessType: SMT; RoHS: Yes; Tolerance: 10%; Vendor: DIGIKEY; Vendor Part#: 490-3897-1-ND; Vendor_Part_No: 490-3897-1-ND; Voltage: 25V; eI Part#: 03_00161_02
CT1 CT9 CT10 = CAP_POL: CAP TANT 100UF 20V 10% 2917; Distributor_name: DIGIKEY; Distributor_part_number: 718-1774-1-ND; EIC Part#: 03_00602_01; Manufacture: Vishay; Manufacture Part Number: TR3D107K020C0080; Manufacture(English): Vishay Dale; Manufacture_Part_Number: TR3D107K020C0080; Manufacturer: Vishay Dale; Manufacturer_Part_No: TR3D107K020C0080; Mfg: Vishay Dale; Mfg Part#: TR3D107K020C0080; Mfr_name: Vishay Dale; Mfr_part_number: TR3D107K020C0080; Oper. Temp. Range: -55C to 125C; Package: 7343; RoHS: Yes; Specifications: CAP TANT 100UF 25V 10% SMD; Vendor: DIGIKEY; Vendor Part#: 718-1774-1-ND; Vendor_Part_No: 718-1774-1-ND; Voltage: 25V; eI Part#: 03_00602_01
D1 D10 D12 = Zener_Diode: TVS 600W 12V UNIDIRECT SMB; Alt Mfg: Diodes Inc; Alt Mfg Part#: SMBJ12A-13-F; Distributor_name: DIGIKEY; Distributor_part_number: SMBJ12A-TPMSCT-ND; EIC Part#: 06_00088_01; Manufacture: Micro Commercial Co; Manufacture Part Number: SMBJ12A-TP; Manufacture(English): Micro Commercial Co; Manufacture_Part_Number: SMBJ12A-TP; Manufacturer: Micro Commercial Co; Manufacturer_Part_No: SMBJ12A-TP; Mfg Part#: 06_00088_01; Mfr_name: Micro Commercial Co; Mfr_part_number: SMBJ12A-TP; Package: DO-214AA, SMB; RoHS: Yes; Specifications: TVS 600W 12V UNIDIRECT SMB; Vendor: DIGIKEY; Vendor Part#: SMBJ12A-TPMSCT-ND; Vendor_Part_No: SMBJ12A-TPMSCT-ND; eI Part#: 06_00088_01
D2 D9 D11 = LED: LED GREEN CLEAR THIN 0805 SMD; Distributor_name: DIGIKEY; Distributor_part_number: 160-1426-1-ND; EIC Part#: 06_00086_01; Manufacture: Lite-On Inc; Manufacture Part Number: LTST-C171KGKT; Manufacture(English): Lite-On Inc; Manufacture_Part_Number: LTST-C171KGKT; Manufacturer: Lite-On Inc; Manufacturer_Part_No: LTST-C171KGKT; Mfg Part#: 06_00086_01; Mfr_name: Lite-On Inc; Mfr_part_number: LTST-C171KGKT; Oper. Temp. Range: -25 to +85C; Package: 0805; RoHS: Yes; Specifications: LED GREEN CLEAR THIN 0805 SMD; Vendor: DIGIKEY; Vendor Part#: 160-1426-1-ND; Vendor_Part_No: 160-1426-1-ND; eI Part#: 06_00086_01
DC_IN1 = Power_Jack: CON PWR JCK 2.5 X 6.5MM VERT; Distributor_name: DIGIKEY; Distributor_part_number: CP-044BH-ND; EIC Part#: TBD; Manufacture: CUI Inc; Manufacture(English): CUI Inc; Manufacturer: CUI Inc; Mfg Part#: TBD; Mfr_name: CUI Inc; Vendor: DIGIKEY; Vendor Part#: CP-044BH-ND; Vendor_Part_No: CP-044BH-ND; eI Part#: TBD
F1 = Fuse: POLYSWITCH RGE SERIES 7.0A HOLD; Distributor_name: DIGIKEY; Distributor_part_number: RGEF700-ND; EIC Part#: TBD; Manufacture: TE Connectivity; Manufacture Part Number: RGEF700; Manufacture(English): TE Connectivity; Manufacture_Part_Number: RGEF700; Manufacturer: TE Connectivity; Manufacturer_Part_No: RGEF700; Mfg: TE Connectivity; Mfg Part#: RGEF700; Mfr_name: TE Connectivity; Mfr_part_number: RGEF700; Package: Radial; Vendor: DIGIKEY; Vendor Part#: RGEF700-ND; Vendor_Part_No: RGEF700-ND; eI Part#: TBD
F2 F3 = Fuse: PTC RESTTBLE 33V 1.50A CHIP 2920; Distributor_name: DIGIKEY; Distributor_part_number: 507-1369-1-ND; EIC Part#: TBD; Manufacture: Bel Fuse Inc; Manufacture(English): Bel Fuse Inc; Manufacturer: Bel Fuse Inc; Mfg: Bel Fuse Inc; Mfg Part#: TBD; Mfr_name: Bel Fuse Inc; Package: 2920; Price @ 1: 0.29000; Price @ 10K: 0.13209; Price @ 1K: 0.13209; Vendor: DIGIKEY; Vendor Part#: 507-1369-1-ND; Vendor_Part_No: 507-1369-1-ND; eI Part#: TBD
FAN1 = 12_WF_4P_BOX_D_0: CONN HEADER 4POS .100 VERT TIN; AVL_Part: AVL; Advansus_Part_Number: 12G080104049; Distributor_name: DIGIKEY; Distributor_part_number: WM4202-ND; EIC Part#: 09_00060_01; Manufacture: Molex Inc; Manufacture(English): Molex Inc; Manufacturer: Molex Inc; Mfg: Molex Inc; Mfg Part#: 09_00060_01; Mfr_name: Molex Inc; Package: WB4P-2.00; Part_Number: 1655000674-01; Price @ 1: 0.37000; Price @ 10K: 0.16192; Price @ 1K: 0.17710; ProcessType: DIP; Vendor: DIGIKEY; Vendor_Part_No: WM4202-ND; eI Part#: 09_00060_01
Q14 = 131_REG_SOT-223_TLV1117_0: IC REG LDO 3.3V 0.8A SOT223; Characteristic: 0.8A; Distributor_name: DIGIKEY; Distributor_part_number: 296-21112-1-ND; EIC Part#: 01_01159_01; Manufacture: TI; Manufacture(English): TI; Manufacturer: TI; Mfg: TI; Mfg Part#: 01_01159_01; Mfr_name: TI; Price @ 1: 0.66000; Price @ 10K: 0.23200; Price @ 1K: 0.26400; ProcessType: SMT; RoHS: Yes; Vendor: DIGIKEY; Vendor Part#: 296-21112-1-ND; Vendor_Part_No: 296-21112-1-ND; eI Part#: 01_01159_01
R54 = 10_R_0: RES 2.2K OHM 1/10W 5% 0402 SMD; Alt Mfg: Yageo; Alt Mfg Part#: RC0402JR-072K2L; Distributor_name: DIGIKEY; Distributor_part_number: P2.2KJCT-ND; EIC Part#: 02_00024_01; Manufacture: Panasonic - ECG; Manufacture Part Number: ERJ-2GEJ222X; Manufacture(English): Panasonic - ECG; Manufacture_Part_Number: ERJ-2GEJ222X; Manufacturer: Panasonic - ECG; Manufacturer_Part_No: ERJ-2GEJ222X; Mfg: Panasonic - ECG; Mfg Part#: 02_00024_01; Mfr_name: Panasonic - ECG; Mfr_part_number: ERJ-2GEJ222X; Oper. Temp. Range: -55C to 125C; Package: 0402; ProcessType: SMT; Remark: Alt part is 1/16W; RoHS: Yes; Specifications: RES 2.2K OHM 1/10W 5% 0402 SMD; Tolerance: 5%; Vendor: DIGIKEY; Vendor Part#: P2.2KJCT-ND; Vendor_Part_No: P2.2KJCT-ND; eI Part#: 02_00316_01
R293 R294 R296 R298 = 10_R_0: RES 4.7K OHM 1/10W 5% 0402 SMD; Alt Mfg: Yageo; Alt Mfg Part#: RC0402JR-074K7L; Distributor_name: DIGIKEY; Distributor_part_number: P4.7KJCT-ND; EIC Part#: 02_00023_01; Manufacture: Panasonic - ECG; Manufacture Part Number: ERJ-2GEJ472X; Manufacture(English): Panasonic - ECG; Manufacture_Part_Number: ERJ-2GEJ472X; Manufacturer: Panasonic - ECG; Manufacturer_Part_No: ERJ-2GEJ472X; Mfg Part#: 02_00023_01; Mfr_name: Panasonic - ECG; Mfr_part_number: ERJ-2GEJ472X; Oper. Temp. Range: -55C to 125C; Package: 0402; ProcessType: SMT; Remark: Alt part is 1/16W; RoHS: Yes; Vendor: DIGIKEY; Vendor Part#: P4.7KJCT-ND; Vendor_Part_No: P4.7KJCT-ND; eI Part#: 02_00023_01
R752 = 10_R_0: RES 10K OHM 1/10W 1% 0402 SMD; Alt Mfg: Yageo; Alt Mfg Part#: RC0402FR-0710KL; Distributor_name: DIGIKEY; Distributor_part_number: P10.0KLCT-ND; EIC Part#: 02_00027_01; Manufacture: Panasonic - ECG; Manufacture Part Number: ERJ-2RKF1002X; Manufacture(English): Panasonic - ECG; Manufacture_Part_Number: ERJ-2RKF1002X; Manufacturer: Panasonic - ECG; Manufacturer_Part_No: ERJ-2RKF1002X; Mfg Part#: 02_00027_01; Mfr_name: Panasonic - ECG; Mfr_part_number: ERJ-2RKF1002X; Oper. Temp. Range: -55C ~ 125C; Package: 0402; Price @ 1: 0.10000; Price @ 10K: 0.00347; Price @ 1K: 0.00672; ProcessType: SMT; Remark: Alt part is 1/16W; RoHS: Yes; Tolerance: 1%; Vendor: DIGIKEY; Vendor Part#: P10.0KLCT-ND; Vendor_Part_No: P10.0KLCT-ND; eI Part#: 02_00027_01
R796 = 10_R_0: RES 2.2K OHM 1/10W 5% 0402 SMD; Alt Mfg: Yageo; Alt Mfg Part#: RC0402JR-072K2L; Distributor_name: DIGIKEY; Distributor_part_number: P2.2KJCT-ND; EIC Part#: 02_00024_01; Manufacture: Panasonic - ECG; Manufacture Part Number: ERJ-2GEJ222X; Manufacture(English): Panasonic - ECG; Manufacture_Part_Number: ERJ-2GEJ222X; Manufacturer: Panasonic - ECG; Manufacturer_Part_No: ERJ-2GEJ222X; Mfg Part#: 02_00024_01; Mfr_name: Panasonic - ECG; Mfr_part_number: ERJ-2GEJ222X; Oper. Temp. Range: -55C to 125C; Package: 0402; ProcessType: SMT; Remark: Alt part is 1/16W; RoHS: Yes; Specifications: RES 2.2K OHM 1/10W 5% 0402 SMD; Tolerance: 5%; Vendor: DIGIKEY; Vendor Part#: P2.2KJCT-ND; Vendor_Part_No: P2.2KJCT-ND; eI Part#: 02_00414_01
R807 = 10_R_0: RES 2.2K OHM 1/10W 5% 0402 SMD; Alt Mfg: Yageo; Alt Mfg Part#: RC0402JR-072K2L; Distributor_name: DIGIKEY; Distributor_part_number: P2.2KJCT-ND; EIC Part#: 02_00024_01; Manufacture: Panasonic - ECG; Manufacture Part Number: ERJ-2GEJ222X; Manufacture(English): Panasonic - ECG; Manufacture_Part_Number: ERJ-2GEJ222X; Manufacturer: Panasonic - ECG; Manufacturer_Part_No: ERJ-2GEJ222X; Mfg Part#: 02_00024_01; Mfr_name: Panasonic - ECG; Mfr_part_number: ERJ-2GEJ222X; Oper. Temp. Range: -55C to 125C; Package: 0402; ProcessType: SMT; Remark: Alt part is 1/16W; RoHS: Yes; Specifications: RES 2.2K OHM 1/10W 5% 0402 SMD; Tolerance: 5%; Vendor: DIGIKEY; Vendor Part#: P2.2KJCT-ND; Vendor_Part_No: P2.2KJCT-ND; eI Part#: 02_00072_01
R823 R832 = 10_R_0: RES 0.0 OHM 1/10W JUMP 0402 SMD; Characteristic: 5%; Distributor_name: DIGIKEY; Distributor_part_number: P0.0JCT-ND; EIC Part#: 02_00019_01; Manufacture: Panasonic - ECG; Manufacture Part Number: ERJ-2GE0R00X; Manufacture(English): Panasonic - ECG; Manufacture_Part_Number: ERJ-2GE0R00X; Manufacturer: Panasonic - ECG; Manufacturer_Part_No: ERJ-2GE0R00X; Mfg: Panasonic Electronic Components; Mfg Part#: 02_00019_01; Mfr_name: Panasonic - ECG; Mfr_part_number: ERJ-2GE0R00X; Mount: NU; Mounting Status: NU; Mounting_Status: NU; Package: 0402; Part_Number: 105A700004; Price @ 1: 0.05000; Price @ 10K: 0.00248; Price @ 1K: 0.00480; ProcessType: SMT; Tolerance: 5%; Vendor: DIGIKEY; Vendor_Part_No: P0.0JCT-ND; eI Part#: 02_00019_01
U66 U70 = TPS22913B: IC LOAD SWITCH 5V 4DSBGA; Distributor_name: DIGIKEY; Distributor_part_number: 296-29697-1-ND; EIC Part#: 01_01129_01; Manufacture: TI; Manufacture(English): TI; Manufacturer: TI; Mfg: TI; Mfg Part#: 01_01129_01; Mfr_name: TI; Price @ 1: 0.89000; Price @ 10K: 0.27000; Price @ 1K: 0.27540; Vendor: DIGIKEY; Vendor_Part_No: 296-29697-1-ND; eI Part#: 01_01129_01

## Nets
3V3_IN_FMC1: R832.2 ; also on sheet 43
3V3_IN_FMC2: R823.2 ; also on sheet 46
12VIN_FMC1: C371.1 CT10.1(Positive) D10.2(CATHODE) F2.2 R807.1 ; also on sheet 43
12VIN_FMC2: C370.1 CT9.1(Positive) D12.2(CATHODE) F3.2 R796.1 ; also on sheet 46
GND: C53.2 C150.1 C219.2 C220.2 C370.2 C371.2 C373.2 C476.1 C820.2 C836.2 C877.2 C900.2 C949.2 C951.2 CN2.3 CN2.4 CN2.57 CN2.58 CN2.63 CN2.64 CN2.117 CN2.118 CN2.H3(SMDFIX_1) CN2.H4(SMDFIX_2) CN2.H5(SMDFIX_3) CN2.H6(SMDFIX_4) CN2.H7(SMDFIX_5) CN2.H8(SMDFIX_6) CN2.H9(SMDFIX_7) CN2.H10(SMDFIX_8) CN2.H11(PTH_1) CN2.H12(PTH_2) CN5.2 CT1.2(Negative) CT9.2(Negative) CT10.2(Negative) D1.1(ANODE) D2.2(T-) D9.2(T-) D10.1(ANODE) D11.2(T-) D12.1(ANODE) DC_IN1.2 DC_IN1.3 FAN1.1 Q14.1(ADJ/GND) R245.1 R598.1 R752.1 U61.4(GND) U66.B1(GND) U70.B1(GND) ; also on sheet 1 2 3 4 5 6 8 10 11 12 13 14 15 16 17 18 19 20 21 22 24 27 28 29 33 34 35 36 37 40 41 42 43 45 46 47
VCC1V8: C476.2 C836.1 CN2.1 CN2.2 R293.2 R294.2 R296.2 R298.2 R578.1 R579.1 U61.1(VCCA) U70.A2(VIN) ; also on sheet 2 6 8 11 19 21 22 27 29 33 34 36 37 41
VCC3V3_AUX: C150.2 C219.1 CN2.61 CN2.62 CN2.119 CN2.120 R78.2 R599.2 R600.2 R603.1 R823.1 R832.1 U66.A2(VIN) ; also on sheet 2 4 6 8 11 12 13 16 18 19 22 27 28 29 33 35 37 40 45 47
VCC3V3_MP_ALT: C373.1 Q14.2(VOUT1) Q14.4(VOUT2) ; also on sheet 5
VCC5: CN2.59 CN2.60 ; also on sheet 8 34 37
VCC12: B12.1 C53.1 C877.1 CT1.1(Positive) D1.2(CATHODE) F1.2 F2.1 F3.1 FAN1.2 R54.1 TP22.1 ; also on sheet 33 34 35
VCC12_AMC: DC_IN1.1 F1.1 ; also on sheet 18
VDD33: C220.1 U66.A1(VOUT) ; also on sheet 33
VDD33_EN: U66.B2(ON) ; also on sheet 37
DSP_I2CBUS_EN: R598.2 U61.5(EN) ; also on sheet 5
EVM_TS_COMPOUT_FPGA_1V8: CN2.113 CN2.116 CN5.5 CN5.7 ; also on sheet 28
EVM_TS_EXTFRAMEEVT_FPGA_1V8: CN9.2 ; also on sheet 28
EVM_TS_SYNCEVT_FPGA_1V8: CN2.115 ; also on sheet 28
EXP_GPIO_00: CN2.54 ; also on sheet 21
EXP_GPIO_01: CN2.56 ; also on sheet 21
EXP_GPIO_02: CN2.66 ; also on sheet 21
EXP_GPIO_03: CN2.68 ; also on sheet 21
EXP_GPIO_04: CN2.70 ; also on sheet 21
EXP_GPIO_05: CN2.72 ; also on sheet 21
EXP_GPIO_06: CN2.74 ; also on sheet 21
EXP_GPIO_07: CN2.76 ; also on sheet 21
EXP_GPIO_08: CN2.78 ; also on sheet 21
EXP_GPIO_09: CN2.80 ; also on sheet 21
EXP_GPIO_10: CN2.82 ; also on sheet 21
EXP_GPIO_11: CN2.84 ; also on sheet 21
EXP_GPIO_12: CN2.86 ; also on sheet 21
EXP_GPIO_13: CN2.88 ; also on sheet 21
EXP_GPIO_14: CN2.90 ; also on sheet 21
EXP_GPIO_15: CN2.92 ; also on sheet 21
EXP_GPIO_16: CN2.94 ; also on sheet 21
EXP_SCL2_3V3: CN2.7 R202.1 R599.1 U61.7(SCLB) ; also on sheet 18
EXP_SDA2_3V3: CN2.5 R201.1 R600.1 U61.6(SDAB) ; also on sheet 18
EXP_TIMO0: CN2.73 ; also on sheet 28
EXP_TIMO1: CN2.77 ; also on sheet 28
EXP_TP0: CN2.96 TP24.1
EXP_TP1: CN2.98 R88.1
EXP_TP2: CN2.100 R82.1
EXP_UART1_RXD_3V3: CN2.95 ; also on sheet 22
EXP_UART1_TXD_3V3: CN2.93 ; also on sheet 22
EXPCON_BDPRESENT_FPGA_1V8_EXP3: CN2.102 ; also on sheet 28
EXPCON_BOARD-ID0_FPGA_1V8_EXP3: CN2.104 ; also on sheet 28
EXPCON_BOARD-ID1_FPGA_1V8_EXP3: CN2.106 ; also on sheet 28
EXPCON_BOARD-ID2_FPGA_1V8_EXP3: CN2.108 ; also on sheet 28
EXPCON_MCU_RESETSTATZ_FPGA_3V3_EXP4: R88.2 ; also on sheet 27
EXT-PS#_FPGA_3V3_EXP4: R78.1 R82.2 ; also on sheet 27
EXT_TIMO1: CN9.1 ; also on sheet 28
FAN_PWM: C900.1 FAN1.4 ; also on sheet 37
GPS_PPS: CN5.1 ; also on sheet 22
LM10011_VID1A: R298.1 U30.AJ28(VCNTL2) ; also on sheet 35
LM10011_VID1B: R296.1 U30.AG27(VCNTL3) ; also on sheet 35
LM10011_VID1C: R294.1 U30.AH27(VCNTL4_VCL) ; also on sheet 35 37
LM10011_VID1S: R293.1 U30.AH26(VCNTL5_VD) ; also on sheet 35 37
PHYSYNC: CN5.8 ; also on sheet 18 29
PW_SEQ_SCL: R202.2 ; also on sheet 4 37
PW_SEQ_SDA: R201.2 ; also on sheet 4 37
RADSYNC: CN5.6 ; also on sheet 18 29
RSV_CLKN: CN2.110 R887.1 ; also on sheet 16
RSV_CLKP: CN2.112 R887.2 ; also on sheet 16
SOC_EMIFA00: CN2.6 ; also on sheet 21
SOC_EMIFA01: CN2.8 ; also on sheet 21
SOC_EMIFA02: CN2.10 ; also on sheet 21
SOC_EMIFA03: CN2.12 ; also on sheet 21
SOC_EMIFA04: CN2.14 ; also on sheet 21
SOC_EMIFA05: CN2.16 ; also on sheet 21
SOC_EMIFA06: CN2.18 ; also on sheet 21
SOC_EMIFA07: CN2.20 ; also on sheet 21
SOC_EMIFA08: CN2.22 ; also on sheet 21
SOC_EMIFA09: CN2.24 ; also on sheet 21
SOC_EMIFA10: CN2.26 ; also on sheet 21
SOC_EMIFA11: CN2.28 ; also on sheet 21
SOC_EMIFA12: CN2.30 ; also on sheet 21
SOC_EMIFA13: CN2.32 ; also on sheet 21
SOC_EMIFA14: CN2.34 ; also on sheet 21
SOC_EMIFA15: CN2.36 ; also on sheet 21
SOC_EMIFA16: CN2.38 ; also on sheet 21
SOC_EMIFA17: CN2.40 ; also on sheet 21
SOC_EMIFA18: CN2.42 ; also on sheet 21
SOC_EMIFA19: CN2.44 ; also on sheet 21
SOC_EMIFA20: CN2.46 ; also on sheet 21
SOC_EMIFA21: CN2.48 ; also on sheet 21
SOC_EMIFA22: CN2.50 ; also on sheet 21
SOC_EMIFA23: CN2.52 ; also on sheet 21
SOC_EMIFBE0Z: CN2.49 ; also on sheet 21
SOC_EMIFBE1Z: CN2.51 ; also on sheet 21
SOC_EMIFCE1Z: CN2.43 ; also on sheet 21
SOC_EMIFCE2Z: CN2.45 ; also on sheet 21
SOC_EMIFCE3Z: CN2.47 ; also on sheet 21
SOC_EMIFD0: CN2.9 ; also on sheet 21
SOC_EMIFD1: CN2.11 ; also on sheet 21
SOC_EMIFD2: CN2.13 ; also on sheet 21
SOC_EMIFD3: CN2.15 ; also on sheet 21
SOC_EMIFD4: CN2.17 ; also on sheet 21
SOC_EMIFD5: CN2.19 ; also on sheet 21
SOC_EMIFD6: CN2.21 ; also on sheet 21
SOC_EMIFD7: CN2.23 ; also on sheet 21
SOC_EMIFD8: CN2.25 ; also on sheet 21
SOC_EMIFD9: CN2.27 ; also on sheet 21
SOC_EMIFD10: CN2.29 ; also on sheet 21
SOC_EMIFD11: CN2.31 ; also on sheet 21
SOC_EMIFD12: CN2.33 ; also on sheet 21
SOC_EMIFD13: CN2.35 ; also on sheet 21
SOC_EMIFD14: CN2.37 ; also on sheet 21
SOC_EMIFD15: CN2.39 ; also on sheet 21
SOC_EMIFOEZ: CN2.53 ; also on sheet 21
SOC_EMIFRNW: CN2.65 ; also on sheet 21
SOC_EMIFWAIT1: CN2.69 ; also on sheet 41
SOC_EMIFWEZ: CN2.55 ; also on sheet 21
SOC_I2C2_SCL: R579.2 U61.2(SCLA) ; also on sheet 29
SOC_I2C2_SDA: R578.2 U61.3(SDAA) ; also on sheet 29
SOC_SSP2_CLK: CN2.91 ; also on sheet 29
SOC_SSP2_CS0: CN2.83 ; also on sheet 29
SOC_SSP2_CS1: CN2.85 ; also on sheet 16
SOC_SSP2_CS2: CN2.87 ; also on sheet 16
SOC_SSP2_CS3: CN2.89 ; also on sheet 16
SOC_SSP2_MISO: R564.1 ; also on sheet 29
SOC_SSP2_MOSI: R565.1 ; also on sheet 29
SOC_TSRXCLKOUT0N: CN2.101 ; also on sheet 28 29
SOC_TSRXCLKOUT0P: CN2.103 ; also on sheet 28 29
SOC_UART1_CTS_3V3: CN2.99 ; also on sheet 8
SOC_UART1_RTS_3V3: CN2.97 ; also on sheet 8
SOC_VPPB_EN_FPGA_1V8_EXP3: R752.2 U70.B2(ON) ; also on sheet 28
TIMI_MUX_OEZ_FPGA_1V8_EXP1: TP113.1 ; also on sheet 28
TIMO0_EVM_FPGA_1V8: CN2.71 ; also on sheet 18 28
TIMO1_EVM_FPGA_1V8: CN2.75 CN5.4 ; also on sheet 28
TSPUSHEVt0: CN2.114 CN5.3
TSPUSHEVt0_E: CN2.109 ; also on sheet 29
TSPUSHEVt1_E: CN2.111 CN5.9 ; also on sheet 29
VPP1V8: C820.1 U70.A1(VOUT) ; also on sheet 36 37
N17748389: CN2.79 R565.2
N17748405: CN2.81 R564.2
N17884504: R603.2 U61.8(VCCB)
N17964069: CN5.10 R252.1
N18333751: B12.2 C949.1 C951.1 Q14.3(VIN)
N18335024: D11.1(B-) R807.2
N18335799: D9.1(B-) R796.2
N18401029: R182.2 U30.Y4(THERMDIODEA1)
N18401050: R373.2 U30.J25(THERMDIODEA2)
N18401071: R589.2 U30.W5(THERMDIODEC1)
N18401092: R374.2 U30.H25(THERMDIODEC2)
N18401143: R182.1 TP36.1
N18401150: R374.1 TP80.1
N18401158: R589.1 TP37.1
N18401168: R373.1 TP79.1
N19607956: D2.1(B-) R54.2
N19755768: R245.2 R252.2 TP57.1

Not connected (* = marked no-connect by the designer): CN2 41* 67* 105* 107* H1(NPTH_1)* H2(NPTH_2)*; FAN1 3*; U30 AJ27(VCNTL0) AK28(VCNTL1)

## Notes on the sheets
sheet 25
- 12v input (fused), 12v to 3p3v MP, K2L VID, 1p8 to VPP1p8
  switch, 3v3Aux to 3v3, FMC1 Power (fuse),
  FMC2 Power (fuse), fan connector
- DC FAN Connector for SOC
- FMC1 POWER
- Over Current
    Protection
- TVS
- Voltage BreakDown = 13.3V
- I(hold) = 1.5A
  I(trip) = 3A
  Trip time= 8s
- 12V to VCC3V3_MP_ALT Generation
- FMC2 POWER
- 3V3_MP @ 150mA
- Over Current
    Protection
- TVS
- Voltage BreakDown = 13.3V
- I(hold) = 1.5A
  I(trip) = 3A
  Trip time= 8s
- VCC1V8 to VPP1V8
- 3V3_AUX to VDD33 Generation
sheet 26
- Expansion Connector, I2C SOC to Expander 1.8v/3.3vAux
- Expansion Connector
- I2C SOC to Expander 1.8v/3.3vAux
- I2C
- I2C bridge to
  Expansion Conn, AMC,
  and PMBus for bus
  monitoring/ unlock
- EMIF
- SWAP
- EMIF
- EMIF
- TIMI
- GPIO
- SPI
- UART
- SOC_UART(3.3V)
- Note: Timer Pins showing which pins go to
   Timer Inputs on the SOC, since all 4 signals
  here are labeled as outputs
